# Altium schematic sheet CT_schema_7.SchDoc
size 251 x 159 mm
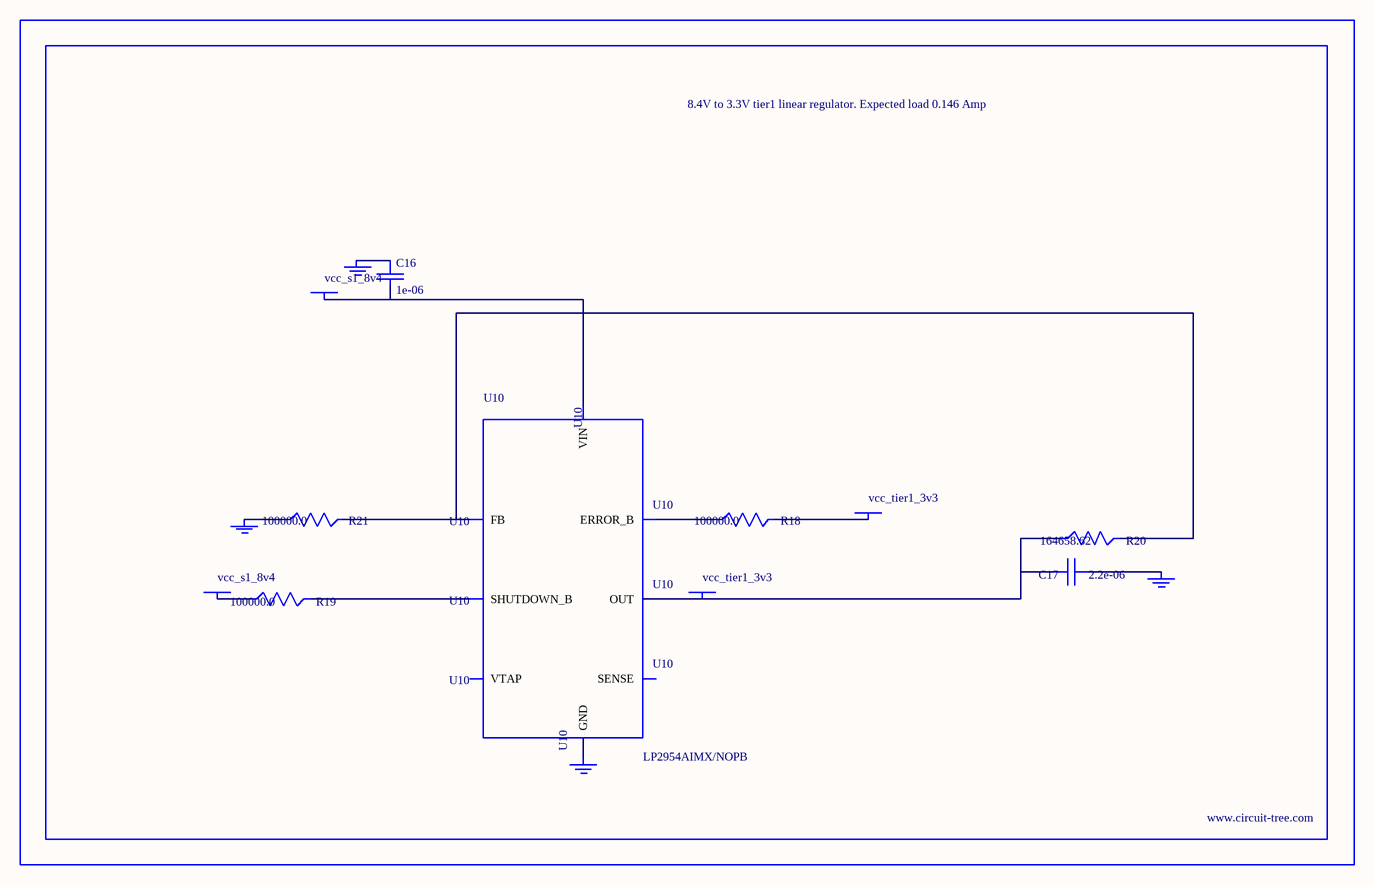
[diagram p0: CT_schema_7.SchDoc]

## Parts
BORDER6  (no value)
C16  1e-06  [EXV-9B]
C17  2.2e-06  [EXV-9B]
GND_INSTANCE_6_0  (no value)
GND_INSTANCE_6_1  (no value)
GND_INSTANCE_6_2  (no value)
GND_INSTANCE_6_3  (no value)
POWER_INSTANCE_6_0  vcc_s1_8v4
POWER_INSTANCE_6_1  vcc_tier1_3v3
POWER_INSTANCE_6_2  vcc_s1_8v4
POWER_INSTANCE_6_3  vcc_tier1_3v3
R18  100000.0  [R0603]
R19  100000.0  [R0603]
R20  164658.62  [R0603]
R21  100000.0  [R0603]
U10  LP2954AIMX/NOPB  [LP2954]

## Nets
NetC16_1: C16.1 GND_INSTANCE_6_2.0(GND)
NetC16_2: C16.2 POWER_INSTANCE_6_2.0(PWR) U10.8(VIN)
NetC17_1: C17.1 GND_INSTANCE_6_0.0(GND)
NetC17_2: C17.2 POWER_INSTANCE_6_3.0(PWR) R20.1 U10.1(OUT)
NetGND_INSTANCE_6_1_0: GND_INSTANCE_6_1.0(GND) R21.1
NetGND_INSTANCE_6_3_0: GND_INSTANCE_6_3.0(GND) U10.4(GND)
NetPOWER_INSTANCE_6_0_0: POWER_INSTANCE_6_0.0(PWR) R19.1
NetPOWER_INSTANCE_6_1_0: POWER_INSTANCE_6_1.0(PWR) R18.2
NetR18_1: R18.1 U10.5(ERROR_B)
NetR19_2: R19.2 U10.3(SHUTDOWN_B)
NetR20_2: R20.2 R21.2 U10.7(FB)

Not connected (* = marked no-connect by the designer): U10 2(SENSE) 6(VTAP)

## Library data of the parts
BORDER6 = BORDER_PAGE6
C16 = EDK105M050A9BAA
C17 = EDK225M050A9BAA
GND_INSTANCE_6_0-GND_INSTANCE_6_3 = GND
POWER_INSTANCE_6_0-POWER_INSTANCE_6_3 = PWR
R18 R19 R21 = RC0603JR-07100KL
R20 = R20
